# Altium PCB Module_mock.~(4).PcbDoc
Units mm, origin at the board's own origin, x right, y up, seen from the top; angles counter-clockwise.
Board outline 43.1 x 56.5 mm, 2 copper layers (Top Layer, Bottom Layer); 2 components, 0 nets, 88 pads, 0 vias.
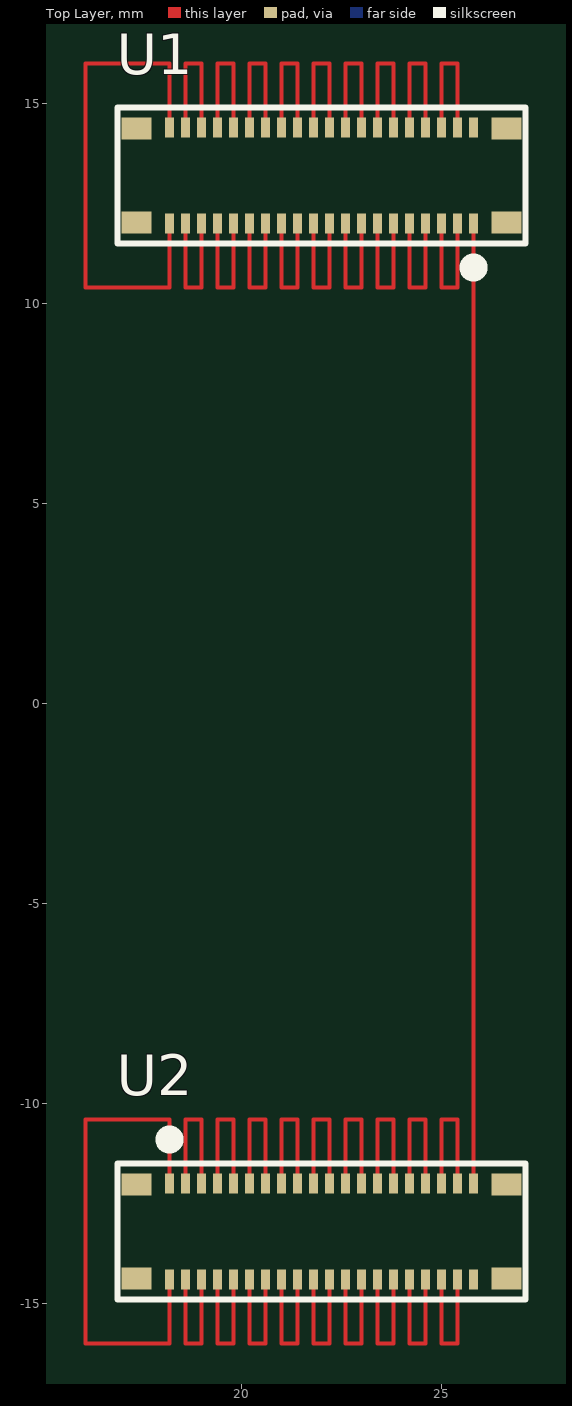
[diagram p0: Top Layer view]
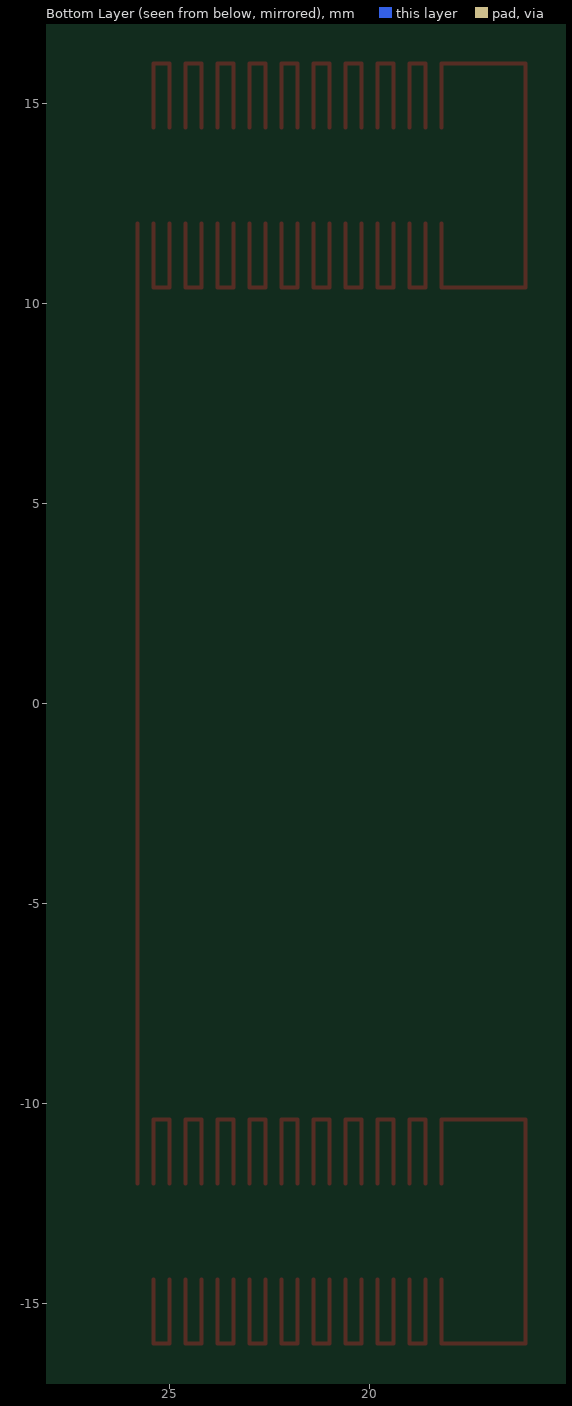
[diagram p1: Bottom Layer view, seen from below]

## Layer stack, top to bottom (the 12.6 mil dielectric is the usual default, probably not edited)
Top Solder: solder mask 0.0102, Solder Resist, Dk 3.5
Top Layer: signal copper 0.0356
Dielectric 1: dielectric 0.32, FR-4, Dk 4.8
Bottom Layer: signal copper 0.0356
Bottom Solder: solder mask 0.0102, Solder Resist, Dk 3.5

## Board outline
0,-28.25 0,28.25 43.1,28.25 43.1,-28.25

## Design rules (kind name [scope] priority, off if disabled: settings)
Clearance [All] p1: gap=0.254 ignorepadtopadclearanceinfootprint=FALSE except(0: Arc-Hole Track-Hole SMDPad-Hole THPad-Hole Via-Hole Fill-Hole Poly-Hole Region-Hole Text-Hole)
PolygonConnect [All] p1: connectstyle=Relief reliefconductorwidth=0.254 reliefentries=4 polygonreliefangle="90 Angle" airgapwidth=0.254
RoutingVias [All] p1: holewidth=0.711 width=1.27 viastyle="Through Hole" minholewidth=0.711 minwidth=1.27 maxholewidth=0.711 maxwidth=1.27
SolderMaskExpansion [All] p1: expansion=0.102 istentingtop=FALSE
Width [All] p1: maxlimit=0.254 minlimit=0.102 preferedwidth=0.254
30 further rules are at their usual default settings.

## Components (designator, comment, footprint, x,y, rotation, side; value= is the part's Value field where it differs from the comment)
U1 "Comment" WP7B-40R 25.8,12 r0 top locked
U2 "Comment" WP7B-40R 18.2,-12 r180 top locked

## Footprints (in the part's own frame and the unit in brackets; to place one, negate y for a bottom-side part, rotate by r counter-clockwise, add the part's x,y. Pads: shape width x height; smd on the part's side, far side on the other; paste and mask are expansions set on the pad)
WP7B-40R [mm]
  rect 0.22x0.5 smd: 1(0,0) 2(-0.4,0) 3(-0.8,0) 4(-1.2,0) 5(-1.6,0) 6(-2,0) 7(-2.4,0) 8(-2.8,0) 9(-3.2,0) 10(-3.6,0) 11(-4,0) 12(-4.4,0) 13(-4.8,0) 14(-5.2,0) 15(-5.6,0) 16(-6,0) 17(-6.4,0) 18(-6.8,0) 19(-7.2,0) 20(-7.6,0) 21(-7.6,2.4) 22(-7.2,2.4) 23(-6.8,2.4) 24(-6.4,2.4) 25(-6,2.4) 26(-5.6,2.4) 27(-5.2,2.4) 28(-4.8,2.4) 29(-4.4,2.4) 30(-4,2.4) 31(-3.6,2.4) 32(-3.2,2.4) 33(-2.8,2.4) 34(-2.4,2.4) 35(-2,2.4) 36(-1.6,2.4) 37(-1.2,2.4) 38(-0.8,2.4) 39(-0.4,2.4) 40(0,2.4)
  rect 0.75x0.55 smd: 41(0.825,0.025) 42(-8.425,0.025) 43(-8.425,2.375) 44(0.825,2.375)
  silkscreen extent -8.9,-1.2 1.3,2.9, body extent -9.1,-0.05 1.5,2.45, height 0.5

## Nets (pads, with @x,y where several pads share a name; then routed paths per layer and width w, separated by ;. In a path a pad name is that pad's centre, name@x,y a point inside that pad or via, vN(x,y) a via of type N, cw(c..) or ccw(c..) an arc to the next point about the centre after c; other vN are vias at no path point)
pads on no net: U1.1 U1.2 U1.3 U1.4 U1.5 U1.6 U1.7 U1.8 U1.9 U1.10 U1.11 U1.12 U1.13 U1.14 U1.15 U1.16 U1.17 U1.18 U1.19 U1.20 U1.21 U1.22 U1.23 U1.24 U1.25 U1.26 U1.27 U1.28 U1.29 U1.30 U1.31 U1.32 U1.33 U1.34 U1.35 U1.36 U1.37 U1.38 U1.39 U1.40 U1.41 U1.42 U1.43 U1.44 U2.1 U2.2 U2.3 U2.4 U2.5 U2.6 U2.7 U2.8 U2.9 U2.10 U2.11 U2.12 U2.13 U2.14 U2.15 U2.16 U2.17 U2.18 U2.19 U2.20 U2.21 U2.22 U2.23 U2.24 U2.25 U2.26 U2.27 U2.28 U2.29 U2.30 U2.31 U2.32 U2.33 U2.34 U2.35 U2.36 U2.37 U2.38 U2.39 U2.40 U2.41 U2.42 U2.43 U2.44
copper on no net: | length 179.6
  Top Layer w0.102: 18.2,-14.4 18.2,-16 16.1,-16 16.1,-10.4 18.2,-10.4 18.2,-12 ; 18.2,12 18.2,10.4 16.1,10.4 16.1,16 18.2,16 18.2,14.4 ; 18.6,-14.4 18.6,-16 19,-16 19,-14.4 ; 18.6,-12 18.6,-10.4 19,-10.4 19,-12 ; 18.6,12 18.6,10.4 19,10.4 19,12 ; 18.6,14.4 18.6,16 19,16 19,14.4 ; 19.4,-14.4 19.4,-16 19.8,-16 19.8,-14.4 ; 19.4,-12 19.4,-10.4 19.8,-10.4 19.8,-12 ; 19.4,12 19.4,10.4 19.8,10.4 19.8,12 ; 19.4,14.4 19.4,16 19.8,16 19.8,14.4 ; 20.2,-14.4 20.2,-16 20.6,-16 20.6,-14.4 ; 20.2,-12 20.2,-10.4 20.6,-10.4 20.6,-12 ; 20.2,12 20.2,10.4 20.6,10.4 20.6,12 ; 20.2,14.4 20.2,16 20.6,16 20.6,14.4 ; 21,-14.4 21,-16 21.4,-16 21.4,-14.4 ; 21,-12 21,-10.4 21.4,-10.4 21.4,-12 ; 21,12 21,10.4 21.4,10.4 21.4,12 ; 21,14.4 21,16 21.4,16 21.4,14.4 ; 21.8,-14.4 21.8,-16 22.2,-16 22.2,-14.4 ; 21.8,-12 21.8,-10.4 22.2,-10.4 22.2,-12 ; 21.8,12 21.8,10.4 22.2,10.4 22.2,12 ; 21.8,14.4 21.8,16 22.2,16 22.2,14.4 ; 22.6,-14.4 22.6,-16 23,-16 23,-14.4 ; 22.6,-12 22.6,-10.4 23,-10.4 23,-12 ; 22.6,12 22.6,10.4 23,10.4 23,12 ; 22.6,14.4 22.6,16 23,16 23,14.4 ; 23.4,-14.4 23.4,-16 23.8,-16 23.8,-14.4 ; 23.4,-12 23.4,-10.4 23.8,-10.4 23.8,-12 ; 23.4,12 23.4,10.4 23.8,10.4 23.8,12 ; 23.4,14.4 23.4,16 23.8,16 23.8,14.4 ; 24.2,-14.4 24.2,-16 24.6,-16 24.6,-14.4 ; 24.2,-12 24.2,-10.4 24.6,-10.4 24.6,-12 ; 24.2,12 24.2,10.4 24.6,10.4 24.6,12 ; 24.2,14.4 24.2,16 24.6,16 24.6,14.4 ; 25,-14.4 25,-16 25.4,-16 25.4,-14.4 ; 25,-12 25,-10.4 25.4,-10.4 25.4,-12 ; 25,12 25,10.4 25.4,10.4 25.4,12 ; 25,14.4 25,16 25.4,16 25.4,14.4 ; 25.8,-12 25.8,12

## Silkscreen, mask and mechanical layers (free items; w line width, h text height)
Mechanical 1:
  the board outline again, w0.102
